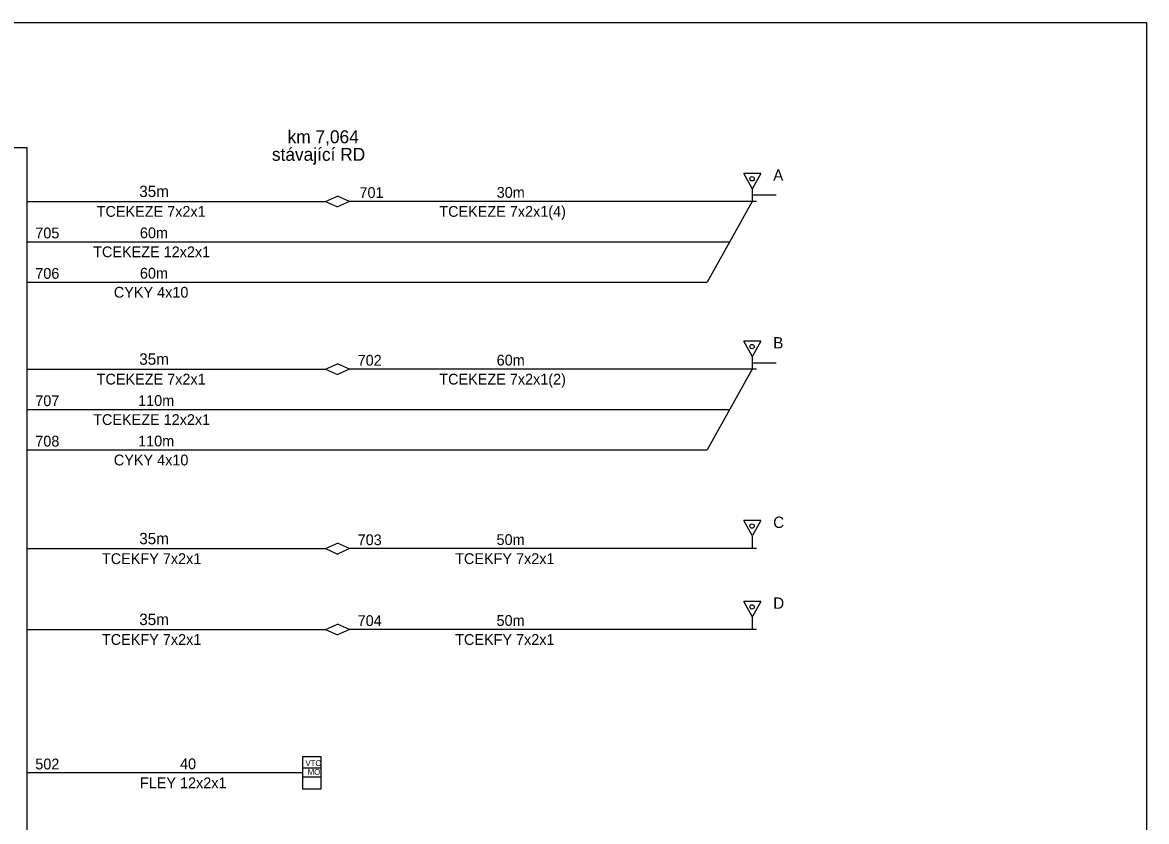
# Model space of a CAD drawing. Extents: x 6137 to 6569, y 2269 to 2566.
# Drawn here: x 6348.3 to 6556.7, y 2417.3 to 2565.5 of the extents above; entities that cross this region are included whole.
import ezdxf

# ---------------------------------------------------------------- set-up
doc = ezdxf.new("R2010")
doc.units = 0
for name, color, linetype in [('Implicitní', 7, 'Continuous'), ('kabelizace', 7, 'Continuous'), ('Schéma kabelů', 7, 'Continuous'), ('Vrstva 1', 7, 'Continuous')]:
    doc.layers.add(name, color=color, linetype=linetype)

msp = doc.modelspace()

# ---------------------------------------------------------------- linework, layer by layer
at = {"layer": 'Implicitní'}
for p, q in [((6485.23, 2537.54), (6482.03, 2537.54)), ((6483.61, 2534.76), (6482.03, 2537.54)), ((6485.23, 2537.54), (6483.65, 2534.76)), ((6483.63, 2534.74), (6483.63, 2532.34)), ((6404.46, 2532.34), (6406.68, 2533.34)), ((6408.9, 2532.34), (6406.68, 2533.34)), ((6483.63, 2533.54), (6488.03, 2533.54)), ((6404.46, 2532.34), (6406.68, 2531.35)), ((6408.9, 2532.34), (6406.68, 2531.35)), ((6484.43, 2532.34), (6482.83, 2532.34)), ((6485.23, 2506.43), (6482.03, 2506.43)), ((6483.61, 2503.65), (6482.03, 2506.43)), ((6485.23, 2506.43), (6483.65, 2503.65)), ((6483.63, 2503.63), (6483.63, 2501.23)), ((6404.46, 2501.23), (6406.68, 2502.22)), ((6408.9, 2501.23), (6406.68, 2502.22)), ((6483.63, 2502.43), (6488.03, 2502.43)), ((6404.46, 2501.23), (6406.68, 2500.24)), ((6408.9, 2501.23), (6406.68, 2500.24)), ((6484.43, 2501.23), (6482.83, 2501.23)), ((6485.23, 2473.13), (6482.03, 2473.13)), ((6483.61, 2470.34), (6482.03, 2473.13)), ((6485.23, 2473.13), (6483.65, 2470.35)), ((6483.63, 2470.33), (6483.63, 2467.93)), ((6404.46, 2467.93), (6406.68, 2468.92)), ((6408.9, 2467.93), (6406.68, 2468.92)), ((6404.46, 2467.93), (6406.68, 2466.93)), ((6408.9, 2467.93), (6406.68, 2466.93)), ((6484.43, 2467.93), (6482.83, 2467.93)), ((6485.23, 2458.13), (6482.03, 2458.13)), ((6483.61, 2455.34), (6482.03, 2458.13)), ((6485.23, 2458.13), (6483.65, 2455.35)), ((6404.46, 2452.93), (6406.68, 2453.92)), ((6408.9, 2452.93), (6406.68, 2453.92)), ((6483.63, 2455.33), (6483.63, 2452.93)), ((6404.46, 2452.93), (6406.68, 2451.93)), ((6408.9, 2452.93), (6406.68, 2451.93)), ((6484.43, 2452.93), (6482.83, 2452.93))]:
    msp.add_line(p, q, dxfattribs=at)
for centre in [(6483.59, 2536.54), (6483.59, 2536.54), (6483.59, 2505.42), (6483.59, 2505.42), (6483.59, 2505.42), (6483.59, 2472.12), (6483.59, 2457.12)]:
    msp.add_circle(centre, 0.4, dxfattribs=at)
at = {"layer": 'kabelizace'}
msp.add_lwpolyline([(6136.73, 2565.55), (6556.73, 2565.55), (6556.73, 2268.55), (6136.73, 2268.55)], close=True, dxfattribs=at)
at = {"layer": 'Schéma kabelů'}
for p, q in [((6349.11, 2532.34), (6404.46, 2532.34)), ((6483.63, 2532.34), (6408.9, 2532.34)), ((6349.11, 2524.84), (6479.44, 2524.84)), ((6349.11, 2517.34), (6475.25, 2517.34)), ((6349.11, 2501.23), (6404.46, 2501.23)), ((6483.63, 2501.23), (6408.9, 2501.23)), ((6349.11, 2493.73), (6479.44, 2493.73)), ((6349.11, 2486.23), (6475.25, 2486.23)), ((6349.11, 2467.93), (6404.46, 2467.93)), ((6483.63, 2467.93), (6408.9, 2467.93)), ((6349.11, 2452.93), (6404.46, 2452.93)), ((6483.63, 2452.93), (6408.9, 2452.93)), ((6400.22, 2426.33), (6349.11, 2426.33)), ((6400.2, 2427.25), (6403.7, 2427.25)), ((6400.21, 2425.61), (6403.71, 2425.61))]:
    msp.add_line(p, q, dxfattribs=at)
msp.add_lwpolyline([(6403.7, 2429.3), (6400.22, 2429.3), (6400.22, 2423.35), (6403.7, 2423.35)], close=True, dxfattribs=at)
at = {"layer": 'Vrstva 1'}
for p, q in [((6483.63, 2532.34), (6475.25, 2517.34)), ((6483.63, 2501.23), (6475.25, 2486.23))]:
    msp.add_line(p, q, dxfattribs=at)
msp.add_lwpolyline([(6349.11, 2361.33), (6337.85, 2361.33), (6337.85, 2542.34), (6349.11, 2542.34)], close=True, dxfattribs=at)

# ---------------------------------------------------------------- texts
at = {"layer": 'Implicitní'}
for s, p in [('A', (6487.5, 2536.18)), ('B', (6487.5, 2505.06)), ('C', (6487.5, 2471.76)), ('D', (6487.5, 2456.76))]:
    msp.add_text(s, height=2.11, rotation=360, dxfattribs=at).set_placement(p)
at = {"layer": 'kabelizace'}
for s, p in [(' km 7,064', (6396.56, 2543.14)), ('stávající RD', (6394.54, 2539.88))]:
    msp.add_text(s, height=2.4, dxfattribs=at).set_placement(p)
at = {"layer": 'Schéma kabelů'}
for p in [(6369.94, 2533.16), (6369.94, 2502.04), (6369.94, 2468.74), (6369.94, 2453.74)]:
    msp.add_text('35m', height=2.112, dxfattribs=at).set_placement(p)
for s, height, p in [('701', 2, (6410.78, 2532.99)), ('705', 2, (6350.66, 2525.49)), ('706', 2, (6350.66, 2517.99)), ('702', 2, (6410.44, 2501.87)), ('707', 2, (6350.66, 2494.37)), ('708', 2, (6350.66, 2486.87)), ('703', 2, (6410.44, 2468.57)), ('704', 2, (6410.44, 2453.57)), ('502', 2, (6350.66, 2426.97)), ('VTO', 1.081, (6400.76, 2427.59)), ('MO', 1.081, (6401.17, 2425.95))]:
    msp.add_text(s, height=height, rotation=360, dxfattribs=at).set_placement(p)
at = {"layer": 'Vrstva 1'}
for s, p in [('30m', (6436.23, 2533.02)), ('TCEKEZE 7x2x1', (6362.04, 2529.49)), ('TCEKEZE 7x2x1(4)', (6425.58, 2529.49)), ('60m', (6370.06, 2525.52)), ('TCEKEZE 12x2x1', (6361.39, 2521.99)), ('60m', (6370.06, 2518.02)), ('CYKY 4x10', (6365.23, 2514.49)), ('60m', (6436.22, 2501.9)), ('TCEKEZE 7x2x1', (6362.04, 2498.37)), ('TCEKEZE 7x2x1(2)', (6425.58, 2498.37)), ('110m', (6369.73, 2494.4)), ('TCEKEZE 12x2x1', (6361.39, 2490.87)), ('110m', (6369.73, 2486.9)), ('CYKY 4x10', (6365.23, 2483.37)), ('50m', (6436.2, 2468.6)), ('TCEKFY 7x2x1', (6363.02, 2465.07)), ('TCEKFY 7x2x1', (6428.52, 2465.07)), ('50m', (6436.2, 2453.6)), ('TCEKFY 7x2x1', (6363.02, 2450.07)), ('TCEKFY 7x2x1', (6428.52, 2450.07)), ('40', (6377.5, 2427)), ('FLEY 12x2x1', (6370.07, 2423.47))]:
    msp.add_text(s, height=2, rotation=360, dxfattribs=at).set_placement(p)

doc.saveas('drawing.dxf')
